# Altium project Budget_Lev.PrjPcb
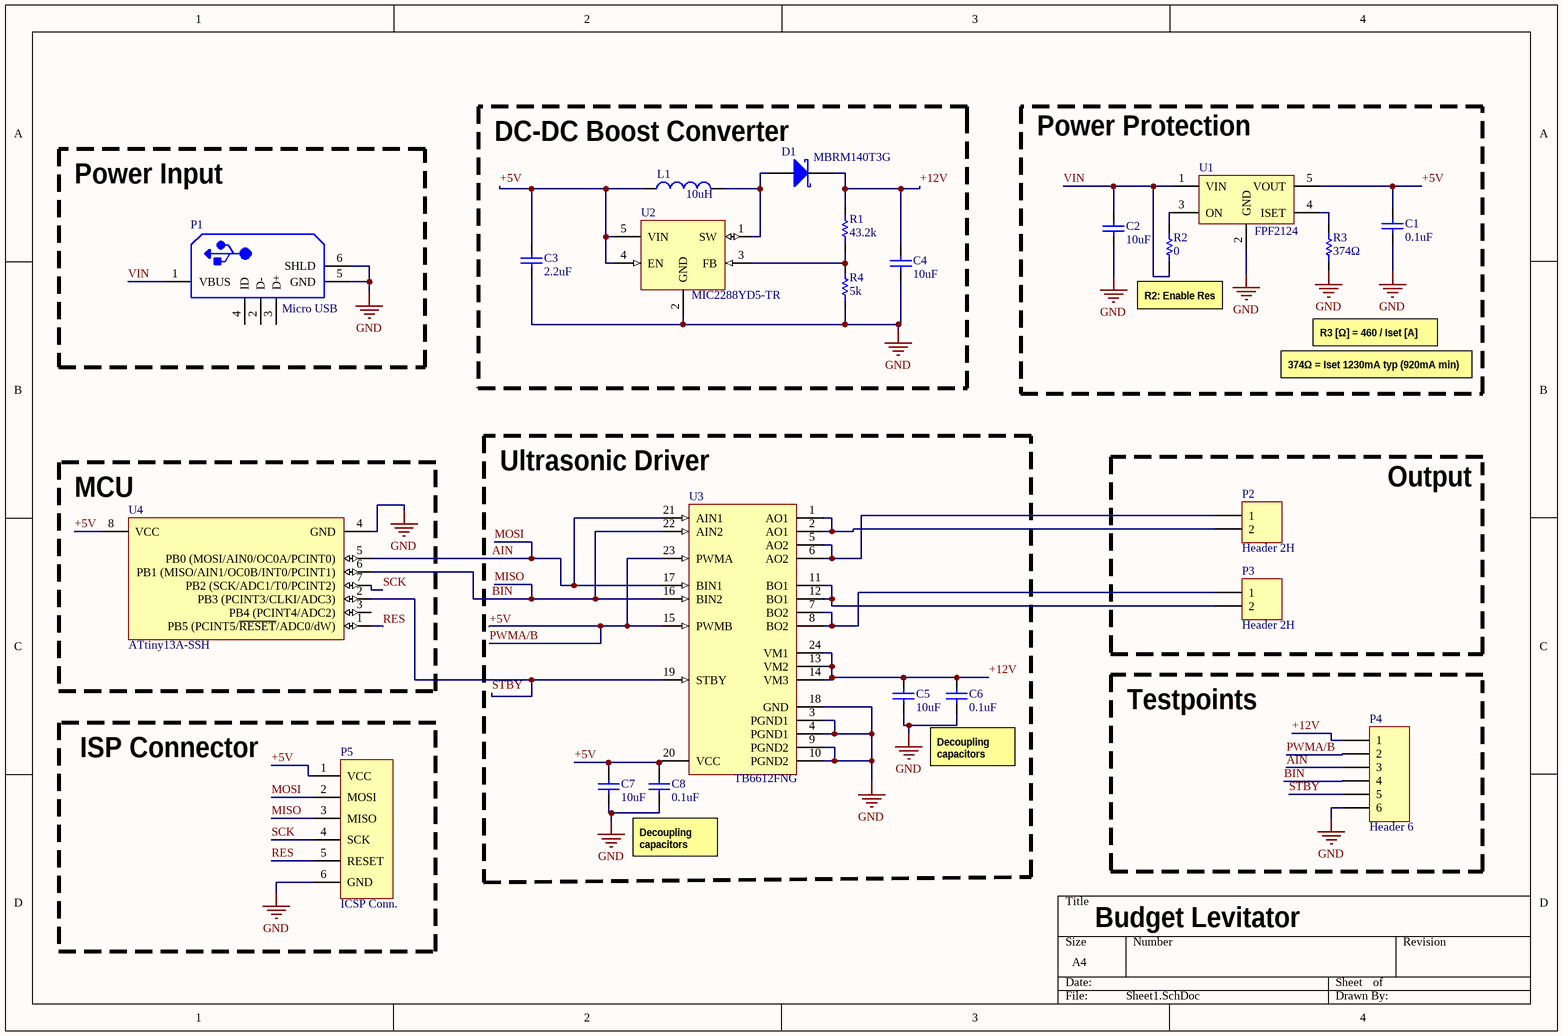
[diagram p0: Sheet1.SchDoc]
1 sheet, 23 parts. Net scope: global (net labels, ports and power ports of the same name join across sheets).
Board file: PCB1.PcbDoc

## Sheet Sheet1.SchDoc
size A4

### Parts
C1  0.1uF  [CAP0805]
C2  10uF  [CAP0805]
C3  2.2uF  [CAP0805]
C4  10uF  [CAP0805]
C5  10uF  [CAP0805]
C6  0.1uF  [CAP0805]
C7  10uF  [CAP0805]
C8  0.1uF  [CAP0805]
D1  MBRM140T3G  [MBRM140T3G]
L1  10uH  [LQH43CN100K03L]
P1  Micro USB  [Micro USB]
P2  Header 2H  [HDR1X2H]
P3  Header 2H  [HDR1X2H]
P4  Header 6  [HDR1X6]
P5  ICSP Conn.  [ICSP Conn.]
R1  43.2k  [RES0805]
R2  0  [RES0805]
R3  374Ω  [RES0805]
R4  5k  [RES0805]
U1  FPF2124  [SOT23-5]
U2  MIC2288YD5-TR  [MIC2288YD5-TR]
U3  TB6612FNG  [TOSH-SSOP-24_M]
U4  ATtiny13A-SSH  [8S1_L]

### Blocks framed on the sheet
Power Protection: C1 C2 R2 R3 U1
Power Input: P1
MCU: U4
Ultrasonic Driver: C5-C8 U3
ISP Connector: P5

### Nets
GND: C1.1 C2.1 C3.1 C4.1 C5.1 C6.1 C7.1 C8.1 P1.5(GND) P1.6(SHLD) P4.6 P5.6(GND) R3.1 R4.1 U1.2(GND) U2.2(GND) U3.3(PGND1) U3.4(PGND1) U3.9(PGND2) U3.10(PGND2) U3.18(GND) U4.4(GND)
+5V: C1.2 C3.2 C7.2 C8.2 L1.1 P4.2 P5.1(VCC) U1.5(VOUT) U2.4(EN) U2.5(VIN) U3.15(PWMB) U3.20(VCC) U3.23(PWMA) U4.8(VCC)  [also labelled PWMA/B]
+12V: C4.2 C5.2 C6.2 D1.1(K) P4.1 R1.2 U3.13(VM2) U3.14(VM3) U3.24(VM1)
AIN: P4.3 P5.2(MOSI) U3.17(BIN1) U3.21(AIN1) U4.5(PB0_(MOSI/AIN0/OC0A/PCINT0))  [also labelled MOSI]
BIN: P4.4 P5.3(MISO) U3.16(BIN2) U3.22(AIN2) U4.6(PB1_(MISO/AIN1/OC0B/INT0/PCINT1))  [also labelled MISO]
RES: P5.5(RESET) U4.1(PB5_(PCINT5/~{RESET}/ADC0/dW))
SCK: P5.4(SCK) U4.7(PB2_(SCK/ADC1/T0/PCINT2))
STBY: P4.5 U3.19(STBY) U4.2(PB3_(PCINT3/CLKI/ADC3))
VIN: C2.2 P1.1(VBUS) R2.1 U1.1(VIN)
NetD1_2: D1.2(A) L1.2 U2.1(SW)
NetP2_1: P2.1 U3.5(AO2) U3.6(AO2)
NetP2_2: P2.2 U3.1(AO1) U3.2(AO1)
NetP3_1: P3.1 U3.7(BO2) U3.8(BO2)
NetP3_2: P3.2 U3.11(BO1) U3.12(BO1)
NetR1_1: R1.1 R4.2 U2.3(FB)
NetR2_2: R2.2 U1.3(ON)
NetR3_2: R3.2 U1.4(ISET)

Not connected (* = marked no-connect by the designer): P1 2(D-) 3(D+) 4(ID); U4 3(PB4_(PCINT4/ADC2))

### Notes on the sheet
- DC-DC Boost Converter
- (near R2) R2: Enable Res
- 374Ω = Iset 1230mA typ (920mA min)
- R3 [Ω] = 460 / Iset [A]
- Output
- Testpoints
- Decoupling capacitors
- Budget Levitator

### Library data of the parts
C1 C2 = Cap: 0603
C3-C8 = CAP
D1 = Diode 10TQ035: Schottky Rectifier; Note: Terminal 2 is the TAB and is electrically connected to the cathode
L1 = Inductor: Code_IEC: 1005; Value: 10mH
P2 P3 = Header 2H: Header, 2-Pin, Right Angle
P4 = Header 6: Header, 6-Pin
R1 R4 = RES
R2 R3 = Resistor: 0603
U3 = CMP-1773-00001-1: Driver IC for Dual DC Motor, 15 V, -20 to 85 degC, 24-Pin SSOP, RoHS, Tape and Reel; Elements: 2; Max Power Dissipation: 200 mW; Max Surge Current: 100 mA; Element Configuration: Common Cathode; Case\Package: TO-236-3; Forward Voltage: 1 V; Peak Reverse Current: 0.1 uA; Forward Current: 70 mA; Recovery Time: 5 ns
U4 = CMP-0093-00145-2: 8-bit AVR Microcontroller, 1.8-5.5V, 20MHz, 1KB Flash, 64 Bytes EEPROM, 64 Bytes SRAM, 8-pin SOIC, Industrial Grade (-40°C to 85°C), Pb-Free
